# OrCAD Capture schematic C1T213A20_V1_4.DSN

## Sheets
1 000_Structure: title: TELINK; rev: V1.4; note: C1T213A20
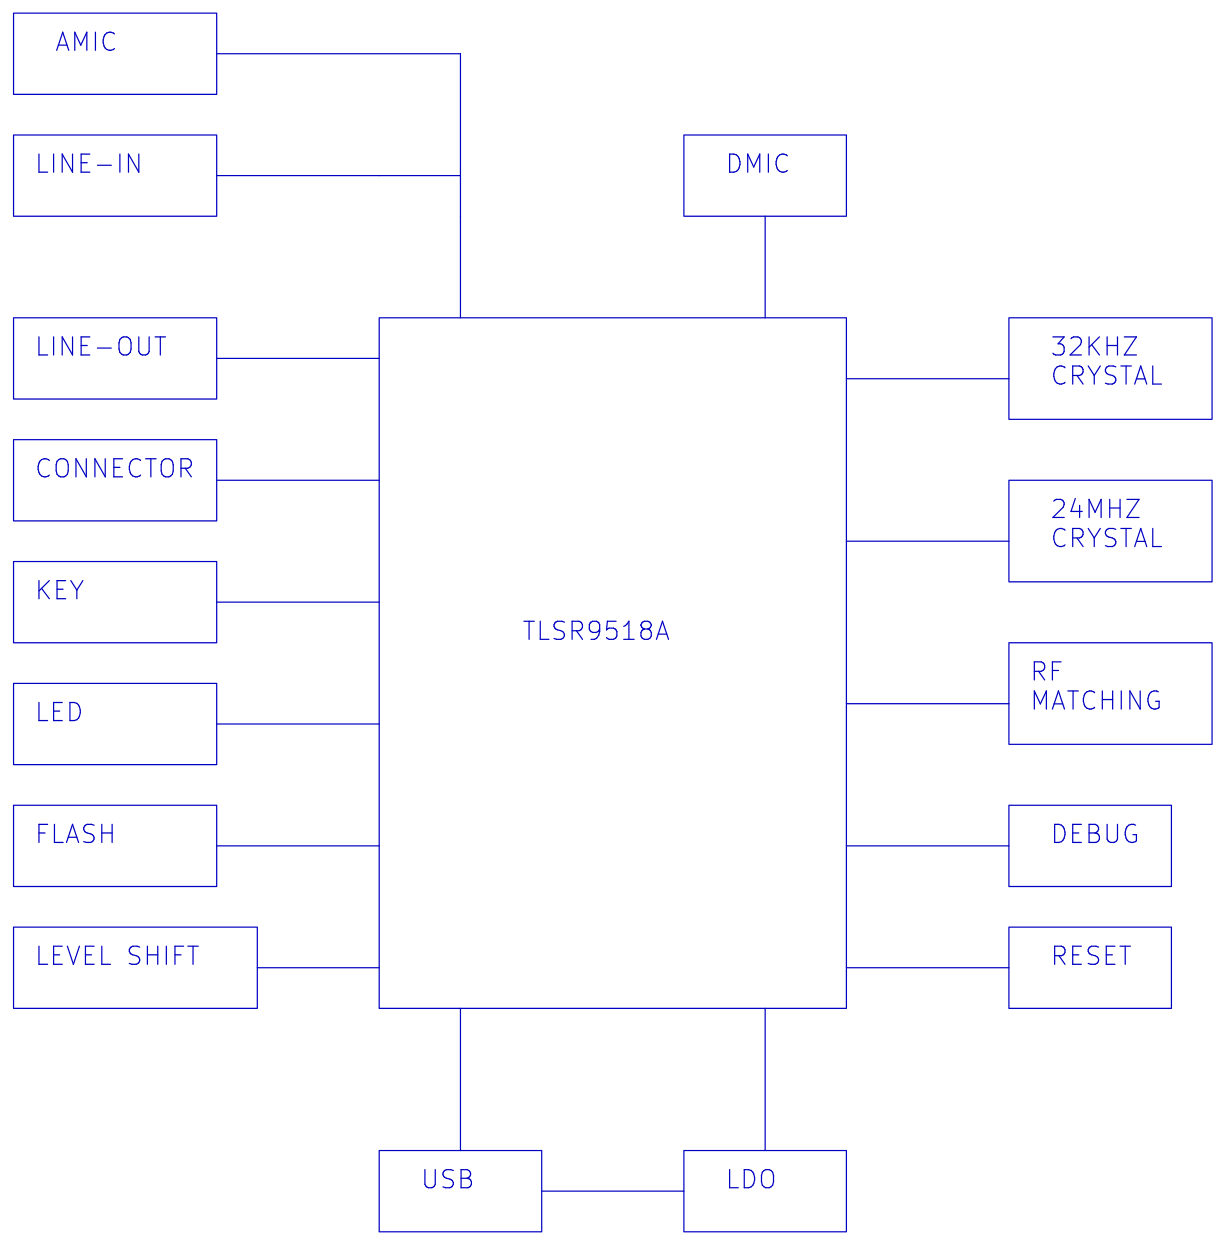
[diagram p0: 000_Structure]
2 002_INTERFACE: size A3
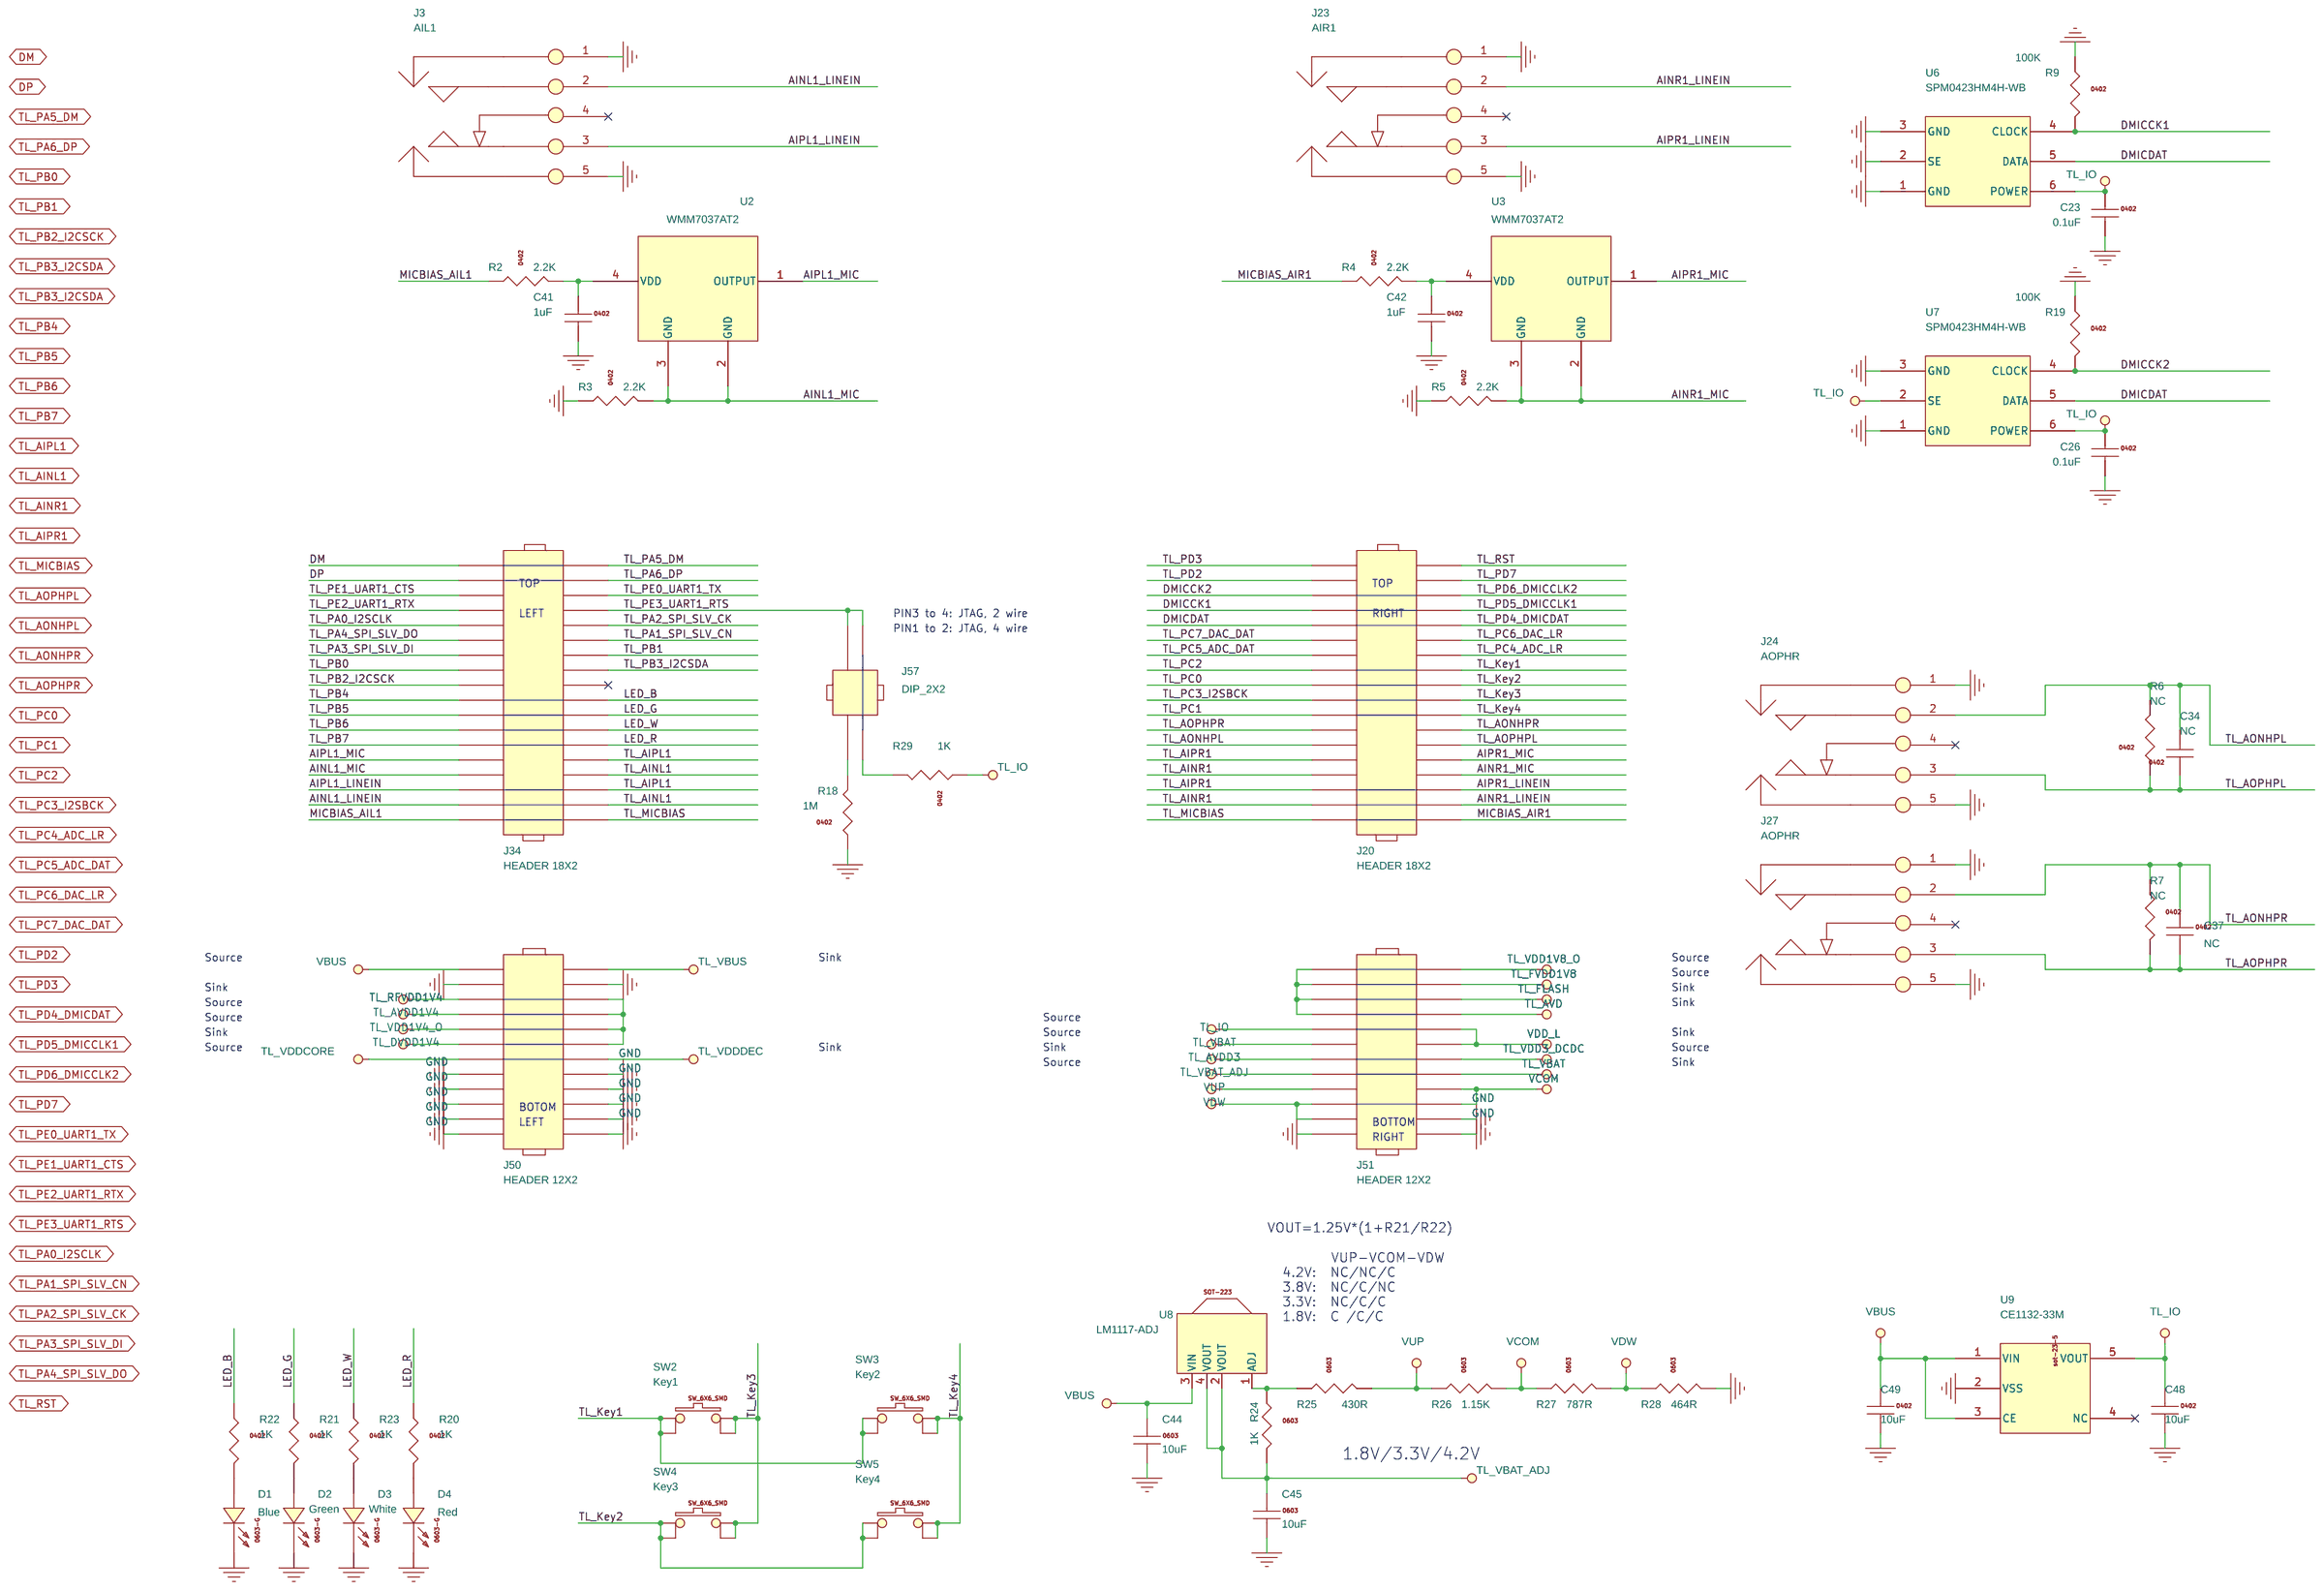
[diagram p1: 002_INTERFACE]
3 000_Log
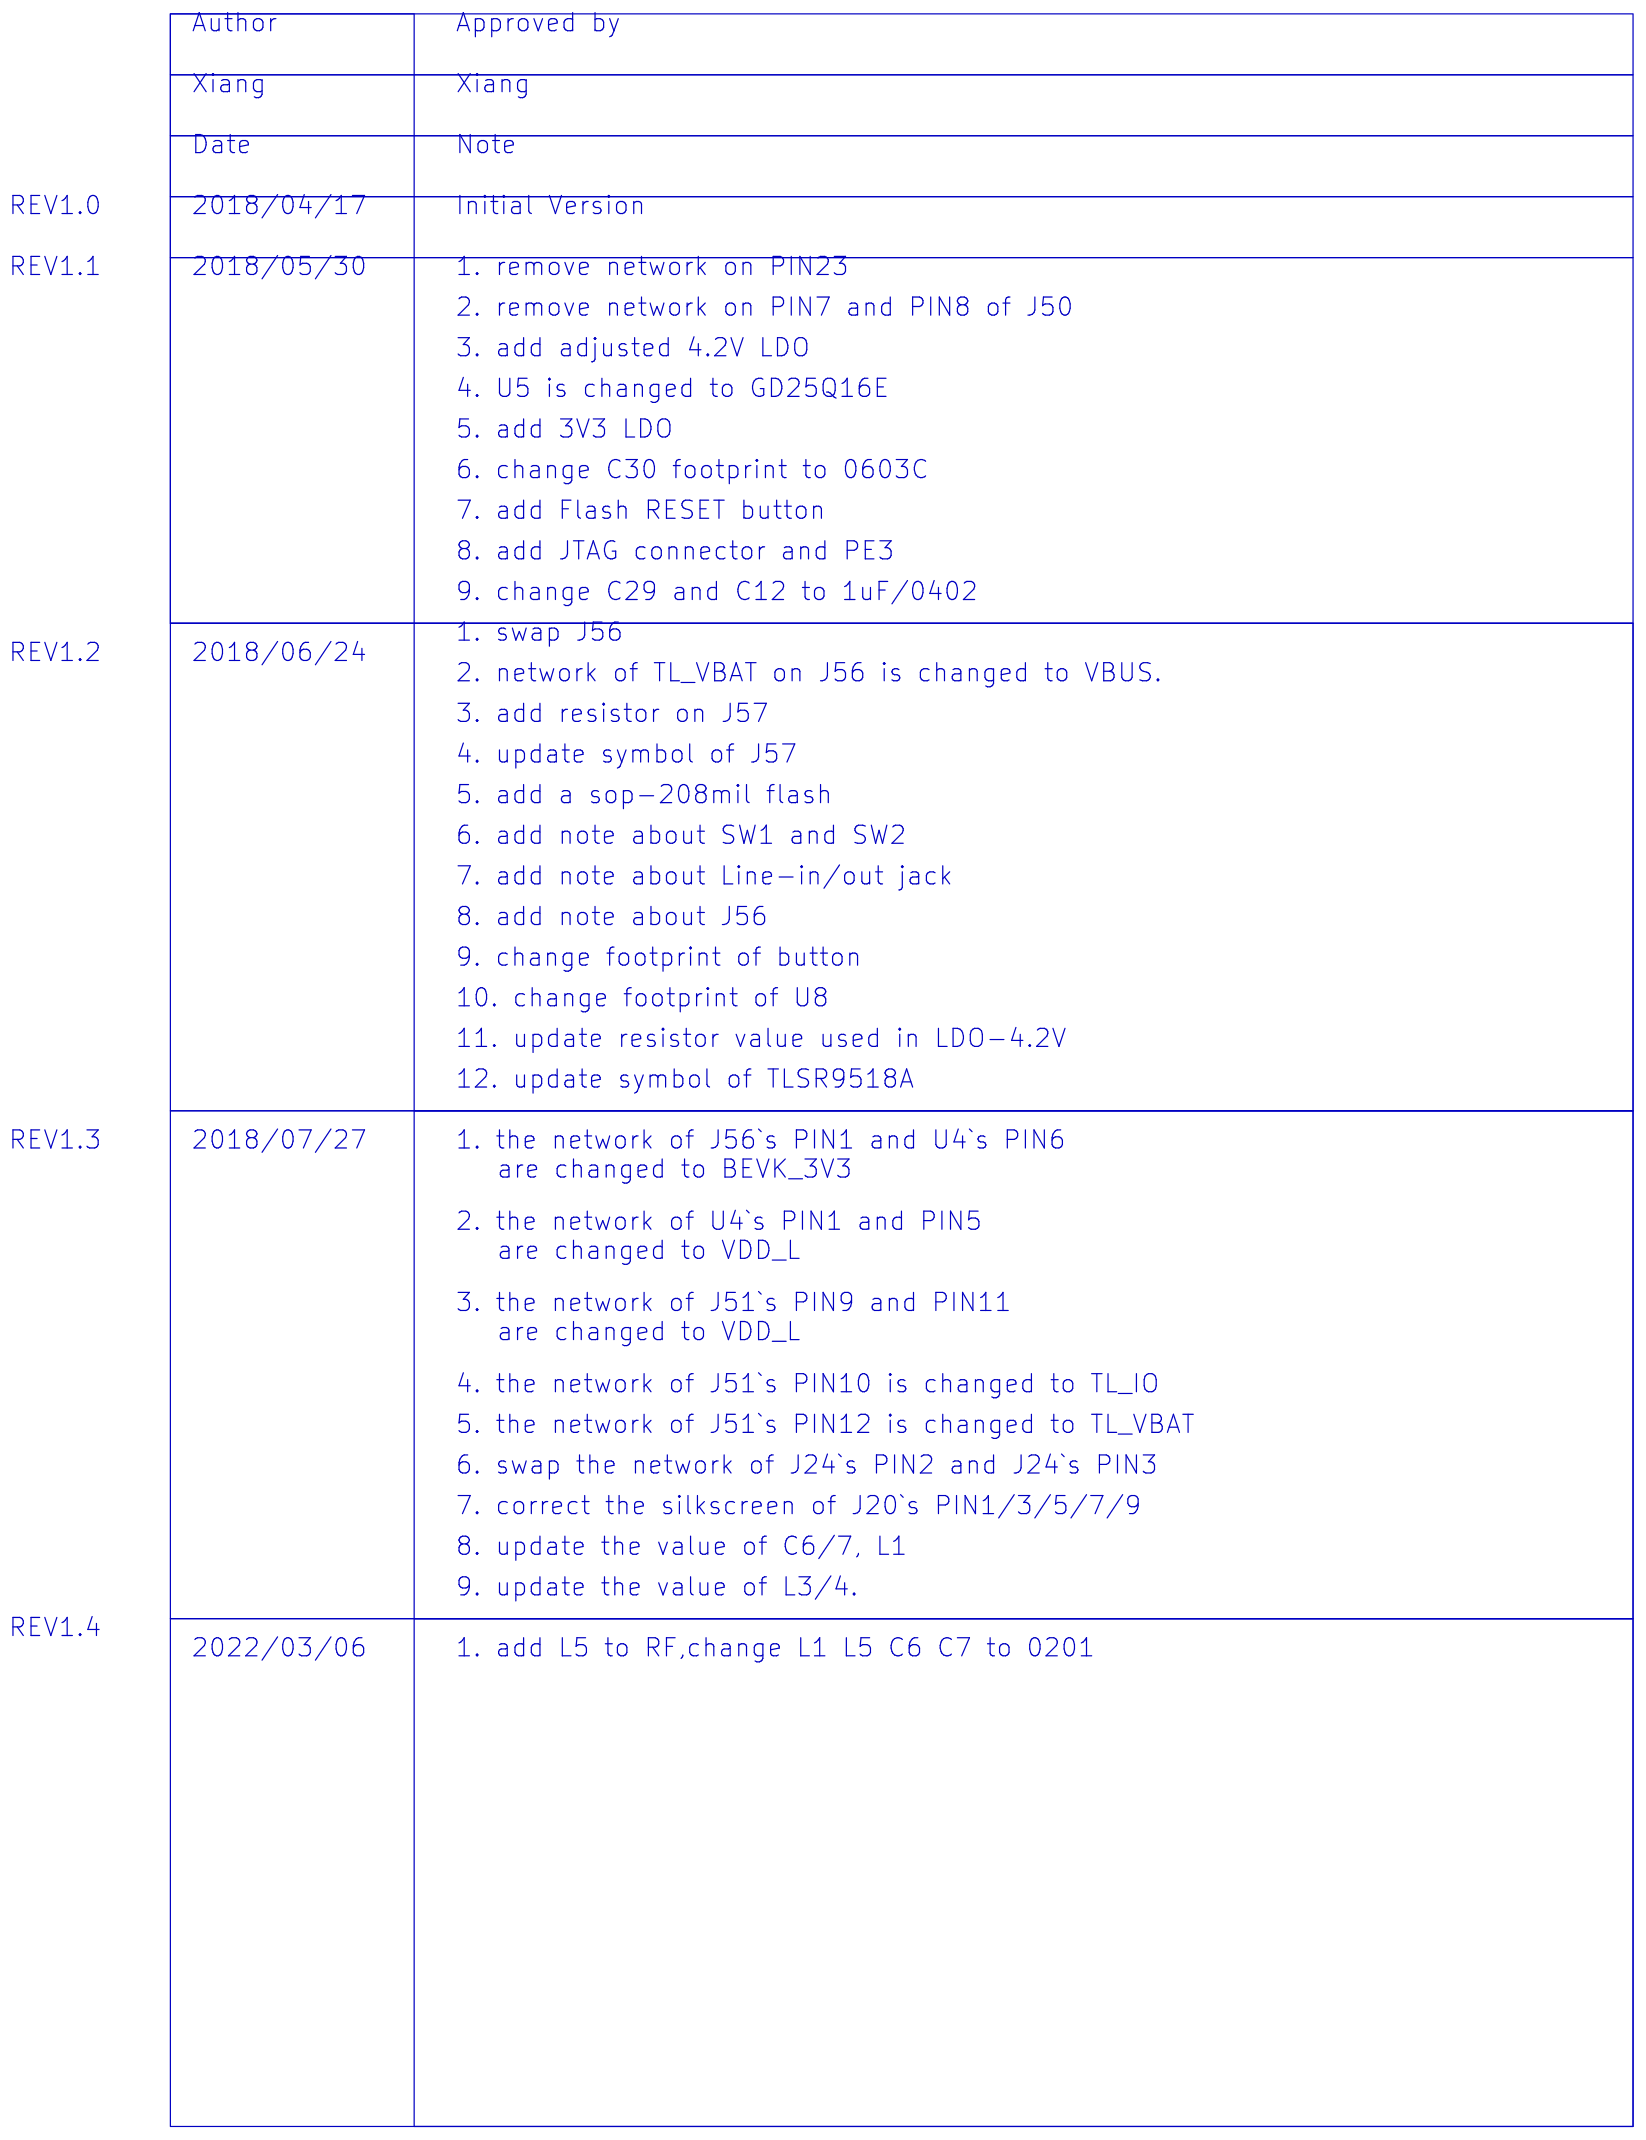
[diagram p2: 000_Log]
4 001_MAIN: size A3
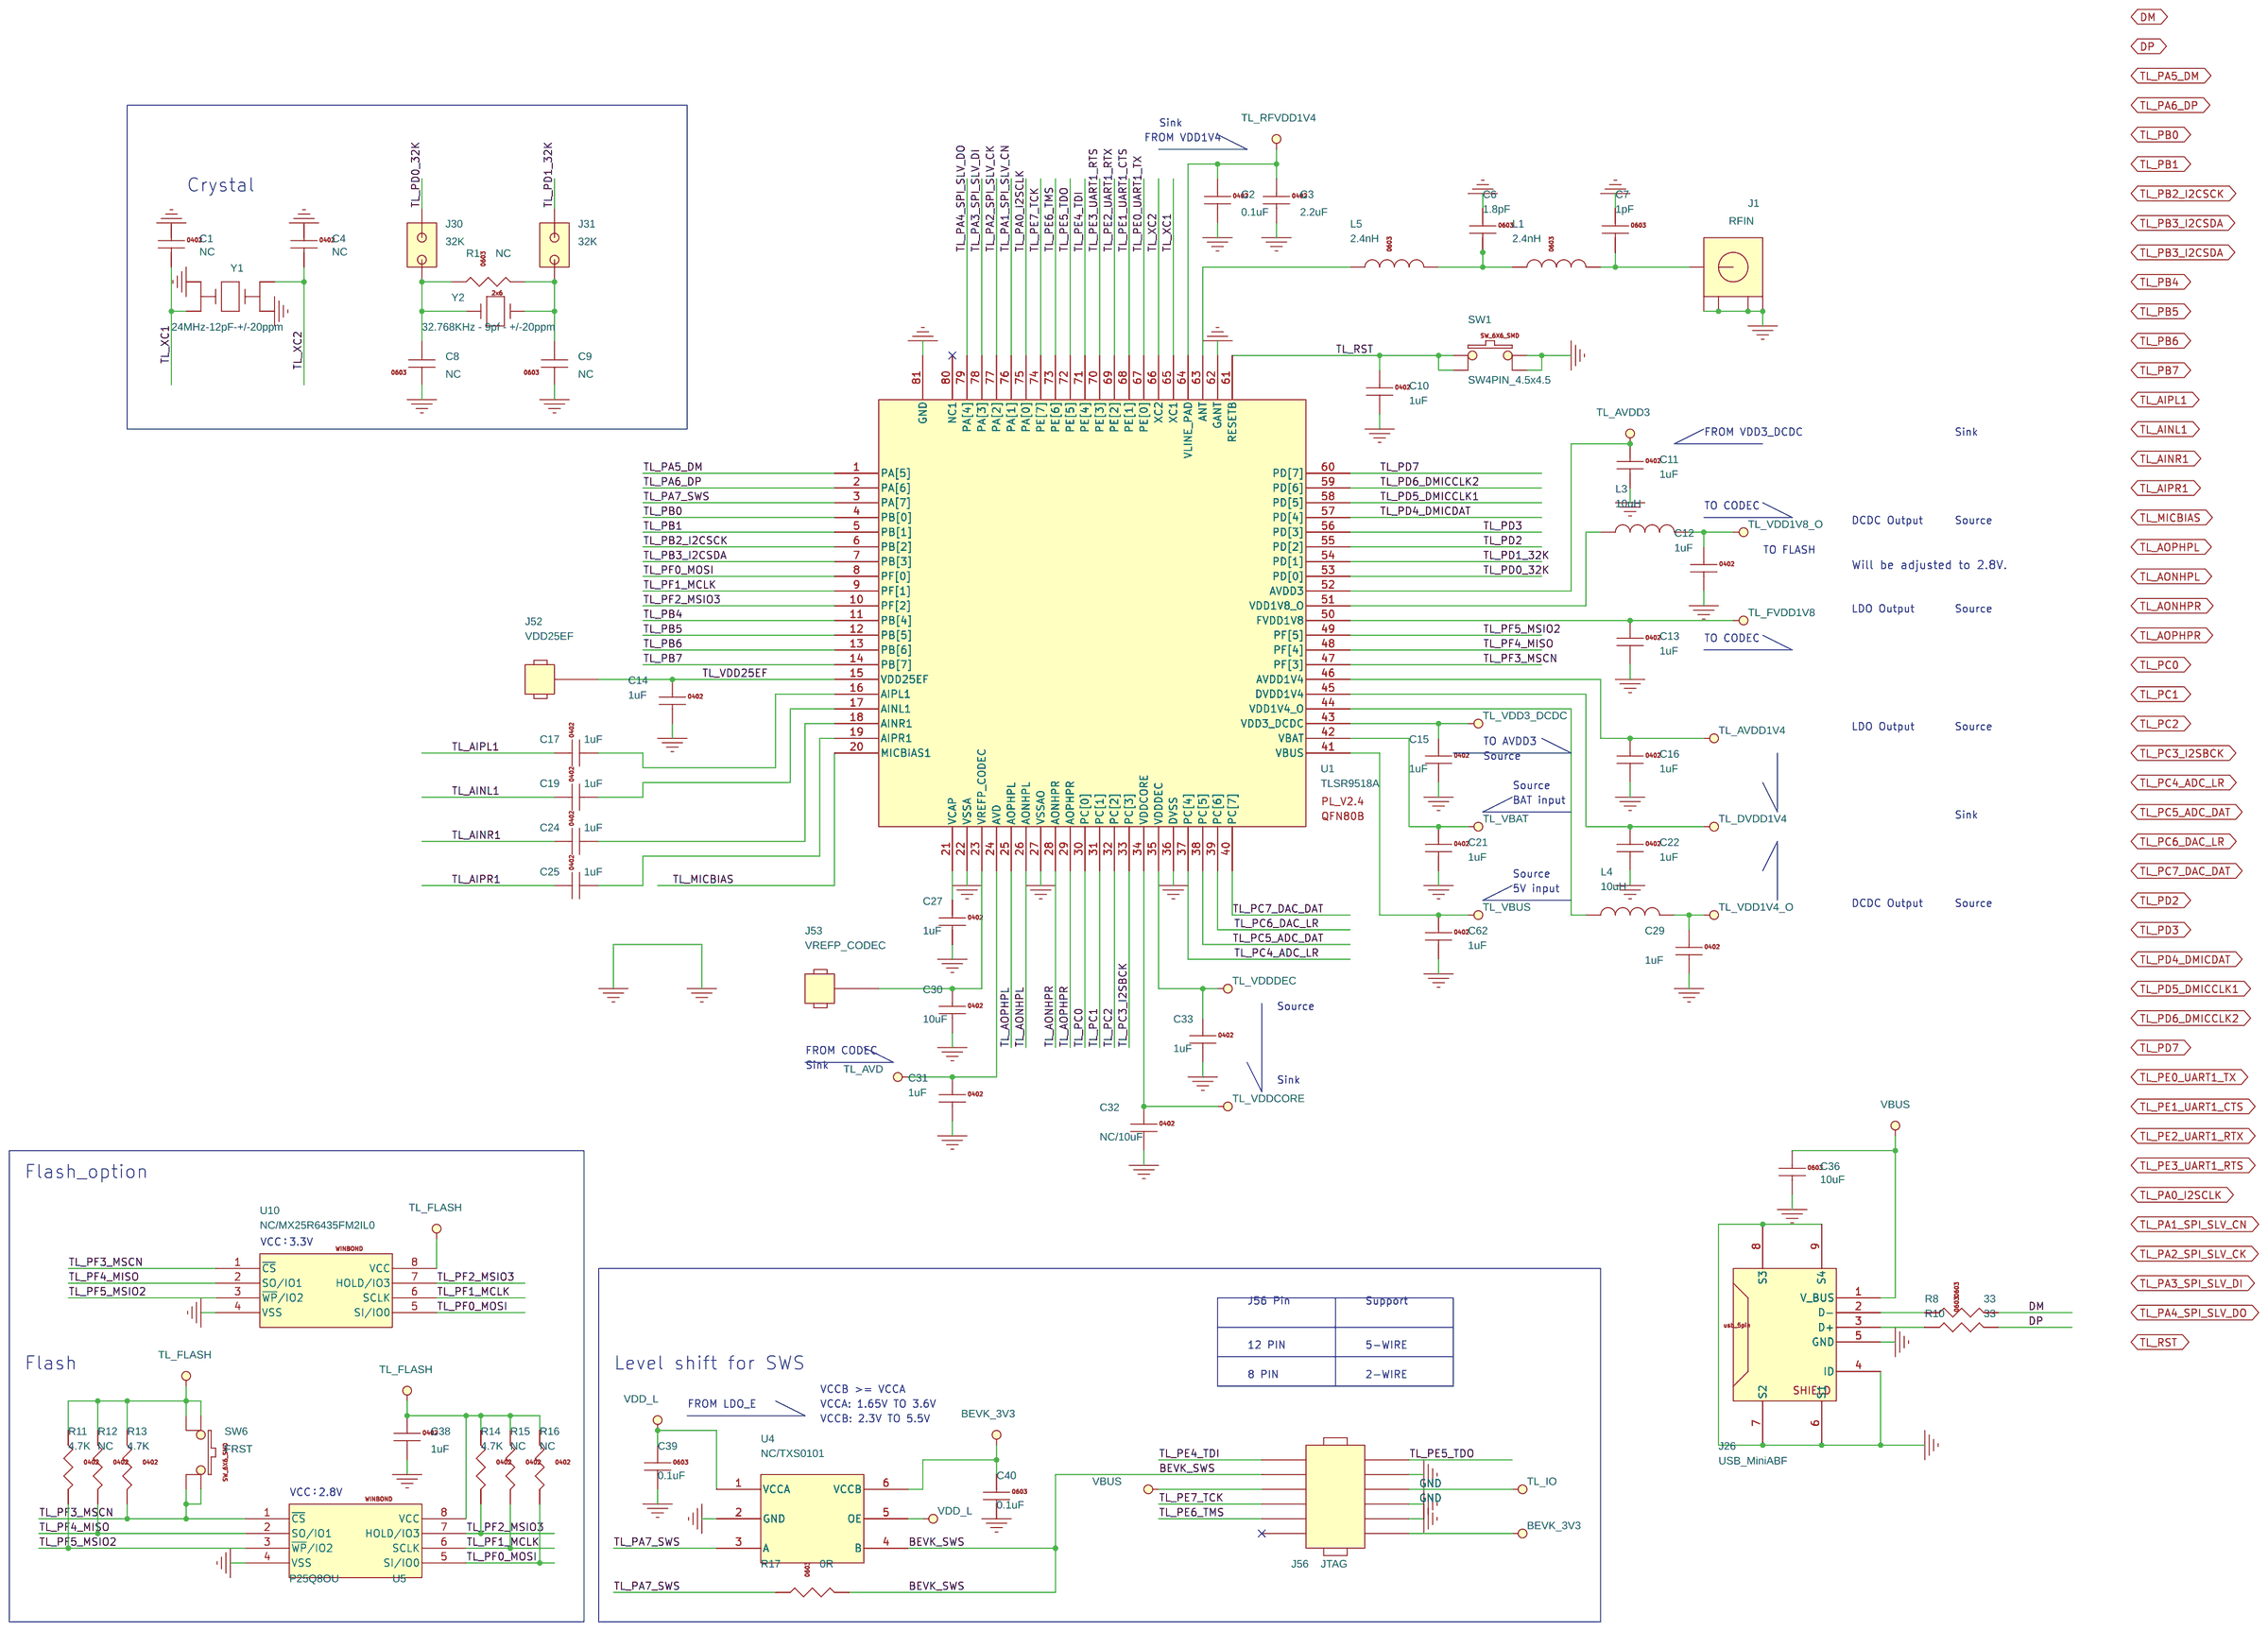
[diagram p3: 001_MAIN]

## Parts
sheet 001_MAIN
C1  NC  [0402]
C2  0.1uF  [0402]
C3  2.2uF  [0402]
C4  NC  [0402]
C6  1.8pF  [0201]
C7  1pF  [0201]
C8  NC  [0402]
C9  NC  [0402]
C10  1uF  [0402]
C11  1uF  [0402]
C12  1uF  [0402]
C13  1uF  [0402]
C14  1uF  [0402]
C15  1uF  [0402]
C16  1uF  [0402]
C17  1uF  [0402]
C19  1uF  [0402]
C21  1uF  [0402]
C22  1uF  [0402]
C24  1uF  [0402]
C25  1uF  [0402]
C27  1uF  [0402]
C29  1uF  [0402]
C30  10uF  [0603C]
C31  1uF  [0402]
C32  NC/10uF  [0603C]
C33  1uF  [0402]
C36  10uF  [0603C]
C38  1uF  [0402]
C39  0.1uF  [0402]
C40  0.1uF  [0402]
C62  1uF  [0402]
J1  RFIN  [SMA-H]
J26  USB_MiniABF  [USB-MINI-F5]
J30  32K  [HDR254F-1X2X850]
J31  32K  [HDR254F-1X2X850]
J52  VDD25EF  [hdr254f-1x1x850]
J53  VREFP_CODEC  [hdr254f-1x1x850]
J56  JTAG  [hdr254f-2x6x850]
L1  2.4nH  [0201]
L3  10uH  [0805L]
L4  10uH  [0805L]
L5  2.4nH  [0201]
R1  NC  [0402]
R8  33  [0402R]
R10  33  [0402R]
R11  4.7K  [0402]
R12  NC  [0402]
R13  4.7K  [0402]
R14  4.7K  [0402]
R15  NC  [0402]
R16  NC  [0402]
R17  0R  [0402R]
SW1  SW4PIN_4.5x4.5  [SW_6X6_SMD]
SW6  FRST  [SW_6X6_SMD]
U1  TLSR9518A  [qfn_9x9_80pin_0p4_6p10x6p10]
U4  NC/TXS0101  [sc70-6]
U5  P25Q8OU  [W25X10_20_40BL]
U10  NC/MX25R6435FM2IL0  [sop8_208mil]
Y1  24MHz-12pF-+/-20ppm  [OSCCC250X320X110]
Y2  32.768KHz - 9pf - +/-20ppm  [OSC_2x6]
sheet 002_INTERFACE
C23  0.1uF  [0402]
C26  0.1uF  [0402]
C34  NC  [0402]
C37  NC  [0402]
C41  1uF  [0402]
C42  1uF  [0402]
C44  10uF  [0603c]
C45  10uF  [0603C]
C48  10uF  [0603C]
C49  10uF  [0603C]
D1  Blue  [0603-LED]
D2  Green  [0603-LED]
D3  White  [0603-LED]
D4  Red  [0603-LED]
J3  AIL1  [PJ-327]
J20  HEADER 18X2  [smd254m-2x18_rx1_30y2_40]
J23  AIR1  [PJ-327]
J24  AOPHR  [PJ-327]
J27  AOPHR  [PJ-327]
J34  HEADER 18X2  [smd254m-2x18_rx1_30y2_40]
J50  HEADER 12X2  [smd254m-2x12_rx1_30y2_40]
J51  HEADER 12X2  [smd254m-2x12_rx1_30y2_40]
J57  DIP_2X2  [DipSwitch_2p54_7p62_2x2]
R2  2.2K  [0402]
R3  2.2K  [0402]
R4  2.2K  [0402]
R5  2.2K  [0402]
R6  NC  [0402]
R7  NC  [0402]
R9  100K  [0402]
R18  1M  [0402]
R19  100K  [0402]
R20  1K  [0402]
R21  1K  [0402]
R22  1K  [0402]
R23  1K  [0402]
R24  1K  [0402]
R25  430R  [0402]
R26  1.15K  [0402]
R27  787R  [0402]
R28  464R  [0402]
R29  1K  [0402]
SW2  Key1  [SW_6X6_SMD]
SW3  Key2  [SW_6X6_SMD]
SW4  Key3  [SW_6X6_SMD]
SW5  Key4  [SW_6X6_SMD]
U2  WMM7037AT2  [ga_bfa423_a83]
U3  WMM7037AT2  [ga_bfa423_a83]
U6  SPM0423HM4H-WB  [DMIC_SPM0423HM4H-WB]
U7  SPM0423HM4H-WB  [DMIC_SPM0423HM4H-WB]
U8  LM1117-ADJ  [sot-223]
U9  CE1132-33M  [sot-23-5]

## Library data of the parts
C1 C4 = C1005_NC
C2 C3 C10-C16 C21-C23 C26 C27 C29-C33 C38 C41 C42 C48 C49 C62 = C1005X5R1C104K
C6-C9 = C1608_NC
C17 C19 C24 C25 C34 C37 = C1005X5R1C105K
C36 C44 = C1608X5R0J106M
C39 C40 C45 = C1608X5R1C105M
J1 = SMA_JACK_2: PART: RF
J26 = USB_MiniABF_5pin
J30 J31 = B2S_3: PAGE: POWER
J52 J53 = HEADER_1
J56 = HEADER_6X2
L1 L5 = MLK1608_000R
L3 L4 = IND
R1 R17 = RS0603K102JT
R8 R10 = RS0603K330JT
R2-R7 R9 R11-R16 R18 R19 R29 = RS0402K104JT
SW1 = SW_6X6_SMD_0
SW2-SW6 = SW_6X6_SMD
U1 = TLSR9518A
U4 = TXS0101
U5 U10 = GD25LD40C_0
Y1 = CRYSTAL4_SM_0
Y2 = OSC_2x6_2pin_16Mhz
D1-D4 = 0603D_Green
J3 J23 J24 J27 = PJ327_2
J20 J34 = HEADER_18X2
J50 J51 = HEADER_12X2
J57 = HEADER_2X2_0
R20-R23 = RS0402K102JT
R24-R28 = RS0603K104JT
U2 U3 = MULPS4CX-RM5_0
U6 U7 = LD1117_SO_0
U8 = XC62FP3302_0.3V_SOT-89
U9 = XC6219_6.3V_SOT-23-5

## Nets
VBUS: C36.1 C44.1 C49.1 J26.1(V_BUS) J50.2 J56.8 U8.3(VIN) U9.1(VIN) U9.3(CE)
VDD_L: C39.1 J51.9 J51.11 U4.1(VCCA) U4.5(OE)
0: C1.1 C2.2 C3.2 C4.1 C6.1 C7.1 C8.1 C9.1 C10.2 C11.2 C12.2 C13.2 C14.2 C15.2 C16.2 C21.2 C22.2 C23.2 C26.2 C27.2 C29.2 C30.2 C31.2 C32.2 C33.2 C36.2 C38.2 C39.2 C40.2 C41.2 C42.2 C44.2 C45.2 C48.2 C49.2 C62.2 D1.C(CATHODE) D2.C(CATHODE) D3.C(CATHODE) D4.C(CATHODE) J1.2 J1.3 J1.4 J1.5 J3.1 J3.5 J23.1 J23.5 J24.1 J24.5 J26.4(ID) J26.5(GND) J26.6(S1) J26.7(S2) J26.8(S3) J26.9(S4) J27.1 J27.5 J50.3 J50.4 J50.15 J50.16 J50.17 J50.18 J50.19 J50.20 J50.21 J50.22 J50.23 J50.24 J51.21 J51.23 J51.24 J56.3 J56.5 J56.9 R3.1 R5.1 R9.1 R18.1 R19.1 R28.2 SW1.3 SW1.4 U1.22(VSSA) U1.27(VSSAO) U1.36(DVSS) U1.62(GANT) U1.81(GND) U4.2(GND) U5.4(VSS) U6.1(GND) U6.2(SE) U6.3(GND) U7.1(GND) U7.3(GND) U9.2(VSS) U10.4(VSS) Y1.2 Y1.4
AINL1_LINEIN: J3.2 J34.34
AINL1_MIC: J34.30 R3.2 U2.2(GND) U2.3(GND)
AINR1_LINEIN: J20.33 J23.2
AINR1_MIC: J20.29 R5.2 U3.2(GND) U3.3(GND)
AIPL1_LINEIN: J3.3 J34.32
AIPL1_MIC: J34.28 U2.1(OUTPUT)
AIPR1_LINEIN: J20.31 J23.3
AIPR1_MIC: J20.27 U3.1(OUTPUT)
BEVK_3V3: C40.1 J56.1 U4.6(VCCB)
BEVK_SWS: J56.10 R17.2 U4.4(B)
DM: R8.2
DM (page 002_INTERFACE): J34.2
DMICCK1: J20.8 R9.2 U6.4(CLOCK)
DMICCK2: J20.6 R19.2 U7.4(CLOCK)
DMICDAT: J20.10 U6.5(DATA) U7.5(DATA)
DP: R10.2
DP (page 002_INTERFACE): J34.4
LED_B: J34.19 R22.1
LED_G: J34.21 R21.1
LED_R: J34.25 R20.1
LED_W: J34.23 R23.1
MICBIAS_AIL1: J34.36 R2.1
MICBIAS_AIR1: J20.35 R4.1
TL_AINL1: C19.1
TL_AINL1 (page 002_INTERFACE): J34.29 J34.33
TL_AINR1: C24.1
TL_AINR1 (page 002_INTERFACE): J20.30 J20.34
TL_AIPL1: C17.1
TL_AIPL1 (page 002_INTERFACE): J34.27 J34.31
TL_AIPR1: C25.1
TL_AIPR1 (page 002_INTERFACE): J20.28 J20.32
TL_AONHPL: U1.26(AONHPL)
TL_AONHPL (page 002_INTERFACE): C34.2 J20.26 J24.2 R6.2
TL_AONHPR: U1.28(AONHPR)
TL_AONHPR (page 002_INTERFACE): C37.1 J20.23 J27.2 R7.1
TL_AOPHPL: U1.25(AOPHPL)
TL_AOPHPL (page 002_INTERFACE): C34.1 J20.25 J24.3 R6.1
TL_AOPHPR: U1.29(AOPHPR)
TL_AOPHPR (page 002_INTERFACE): C37.2 J20.24 J27.3 R7.2
TL_AVD: C31.1 J51.7 U1.24(AVD)
TL_AVDD1V4: C16.1 J50.8 U1.46(AVDD1V4)
TL_AVDD3: C11.1 J51.14 U1.52(AVDD3)
TL_DVDD1V4: C22.1 J50.12 U1.45(DVDD1V4)
TL_FLASH: C38.1 J51.5 R11.1 R12.1 R13.1 R14.1 R15.1 R16.1 SW6.1 SW6.2 U5.8(VCC) U10.8(VCC)
TL_FVDD1V8: C13.1 J51.3 U1.50(FVDD1V8)
TL_IO: C23.1 C26.1 C48.1 J51.10 J56.7 R29.1 U6.6(POWER) U7.2(SE) U7.6(POWER) U9.5(VOUT)
TL_Key1: J20.15 SW2.1 SW2.2 SW3.1 SW3.2
TL_Key2: J20.17 SW4.1 SW4.2 SW5.1 SW5.2
TL_Key3: J20.19 SW2.3 SW2.4 SW4.3 SW4.4
TL_Key4: J20.21 SW3.3 SW3.4 SW5.3 SW5.4
TL_MICBIAS: U1.20(MICBIAS1)
TL_MICBIAS (page 002_INTERFACE): J20.36 J34.35
TL_PA0_I2SCLK: U1.75(PA[0])
TL_PA0_I2SCLK (page 002_INTERFACE): J34.10
TL_PA1_SPI_SLV_CN: U1.76(PA[1])
TL_PA1_SPI_SLV_CN (page 002_INTERFACE): J34.11
TL_PA2_SPI_SLV_CK: U1.77(PA[2])
TL_PA2_SPI_SLV_CK (page 002_INTERFACE): J34.9
TL_PA3_SPI_SLV_DI: U1.78(PA[3])
TL_PA3_SPI_SLV_DI (page 002_INTERFACE): J34.14
TL_PA4_SPI_SLV_DO: U1.79(PA[4])
TL_PA4_SPI_SLV_DO (page 002_INTERFACE): J34.12
TL_PA5_DM: U1.1(PA[5])
TL_PA5_DM (page 002_INTERFACE): J34.1
TL_PA6_DP: U1.2(PA[6])
TL_PA6_DP (page 002_INTERFACE): J34.3
TL_PA7_SWS: R17.1 U1.3(PA[7]) U4.3(A)
TL_PB0: U1.4(PB[0])
TL_PB0 (page 002_INTERFACE): J34.16
TL_PB1: U1.5(PB[1])
TL_PB1 (page 002_INTERFACE): J34.13
TL_PB2_I2CSCK: U1.6(PB[2])
TL_PB2_I2CSCK (page 002_INTERFACE): J34.18
TL_PB3_I2CSDA: U1.7(PB[3])
TL_PB3_I2CSDA (page 002_INTERFACE): J34.15
TL_PB4: U1.11(PB[4])
TL_PB4 (page 002_INTERFACE): J34.20
TL_PB5: U1.12(PB[5])
TL_PB5 (page 002_INTERFACE): J34.22
TL_PB6: U1.13(PB[6])
TL_PB6 (page 002_INTERFACE): J34.24
TL_PB7: U1.14(PB[7])
TL_PB7 (page 002_INTERFACE): J34.26
TL_PC0: U1.30(PC[0])
TL_PC0 (page 002_INTERFACE): J20.18
TL_PC1: U1.31(PC[1])
TL_PC1 (page 002_INTERFACE): J20.22
TL_PC2: U1.32(PC[2])
TL_PC2 (page 002_INTERFACE): J20.16
TL_PC3_I2SBCK: U1.33(PC[3])
TL_PC3_I2SBCK (page 002_INTERFACE): J20.20
TL_PC4_ADC_LR: U1.37(PC[4])
TL_PC4_ADC_LR (page 002_INTERFACE): J20.13
TL_PC5_ADC_DAT: U1.38(PC[5])
TL_PC5_ADC_DAT (page 002_INTERFACE): J20.14
TL_PC6_DAC_LR: U1.39(PC[6])
TL_PC6_DAC_LR (page 002_INTERFACE): J20.11
TL_PC7_DAC_DAT: U1.40(PC[7])
TL_PC7_DAC_DAT (page 002_INTERFACE): J20.12
TL_PD0_32K: J30.2 U1.53(PD[0])
TL_PD1_32K: J31.2 U1.54(PD[1])
TL_PD2: U1.55(PD[2])
TL_PD2 (page 002_INTERFACE): J20.4
TL_PD3: U1.56(PD[3])
TL_PD3 (page 002_INTERFACE): J20.2
TL_PD4_DMICDAT: U1.57(PD[4])
TL_PD4_DMICDAT (page 002_INTERFACE): J20.9
TL_PD5_DMICCLK1: U1.58(PD[5])
TL_PD5_DMICCLK1 (page 002_INTERFACE): J20.7
TL_PD6_DMICCLK2: U1.59(PD[6])
TL_PD6_DMICCLK2 (page 002_INTERFACE): J20.5
TL_PD7: U1.60(PD[7])
TL_PD7 (page 002_INTERFACE): J20.3
TL_PE0_UART1_TX: U1.67(PE[0])
TL_PE0_UART1_TX (page 002_INTERFACE): J34.5
TL_PE1_UART1_CTS: U1.68(PE[1])
TL_PE1_UART1_CTS (page 002_INTERFACE): J34.6
TL_PE2_UART1_RTX: U1.69(PE[2])
TL_PE2_UART1_RTX (page 002_INTERFACE): J34.8
TL_PE3_UART1_RTS: U1.70(PE[3])
TL_PE3_UART1_RTS (page 002_INTERFACE): J34.7 J57.1 J57.3
TL_PE4_TDI: J56.12 U1.71(PE[4])
TL_PE5_TDO: J56.11 U1.72(PE[5])
TL_PE6_TMS: J56.4 U1.73(PE[6])
TL_PE7_TCK: J56.6 U1.74(PE[7])
TL_PF0_MOSI: R16.2 U1.8(PF[0]) U5.5(SI/IO0) U10.5(SI/IO0)
TL_PF1_MCLK: R15.2 U1.9(PF[1]) U5.6(SCLK) U10.6(SCLK)
TL_PF2_MSIO3: R14.2 U1.10(PF[2]) U5.7(HOLD/IO3) U10.7(HOLD/IO3)
TL_PF3_MSCN: R13.2 SW6.3 SW6.4 U1.47(PF[3]) U5.1(~{CS}) U10.1(~{CS})
TL_PF4_MISO: R12.2 U1.48(PF[4]) U5.2(SO/IO1) U10.2(SO/IO1)
TL_PF5_MSIO2: R11.2 U1.49(PF[5]) U5.3(~{WP}/IO2) U10.3(~{WP}/IO2)
TL_RFVDD1V4: C2.1 C3.1 J50.6 U1.64(VLINE_PAD)
TL_RST: C10.1 SW1.1 SW1.2 U1.61(RESETB)
TL_RST (page 002_INTERFACE): J20.1
TL_VBAT: C21.1 J51.12 J51.15 U1.42(VBAT)
TL_VBAT_ADJ: C45.1 J51.16 R24.2 U8.2(VOUT) U8.4(VOUT)
TL_VBUS: C62.1 J50.1 U1.41(VBUS)
TL_VDD1V4_O: C29.1 J50.10 L4.2
TL_VDD1V8_O: C12.1 J51.1 L3.2
TL_VDD3_DCDC: C15.1 J51.13 U1.43(VDD3_DCDC)
TL_VDD25EF: C14.1 J52.1 U1.15(VDD25EF)
TL_VDDCORE: C32.1 J50.14 U1.34(VDDCORE)
TL_VDDDEC: C33.1 J50.13 U1.35(VDDDEC)
TL_XC1: C1.2 U1.65(XC1) Y1.3
TL_XC2: C4.2 U1.66(XC2) Y1.1
VCOM: J51.17 J51.19 R26.2 R27.1
VDW: J51.20 J51.22 R27.2 R28.1
VUP: J51.18 R25.2 R26.1
N19754780: J26.3(D+) R10.1
N19754798: J26.2(D-) R8.1
N19860865: C8.2 J30.1 R1.1 Y2.1
N19860867: C9.2 J31.1 R1.2 Y2.2
N19861195: C24.2 U1.18(AINR1)
N19861200: C25.2 U1.19(AIPR1)
N19861219: C30.1 J53.1 U1.23(VREFP_CODEC)
N19861425: C19.2 U1.17(AINL1)
N19861431: C17.2 U1.16(AIPL1)
N19861467: C27.1 U1.21(VCAP)
N19861531: L3.1 U1.51(VDD1V8_O)
N19861571: L4.1 U1.44(VDD1V4_O)
N19870648: R24.1 R25.1 U8.1(ADJ)
N19912632: C42.1 R4.2 U3.4(VDD)
N19912698: C41.1 R2.2 U2.4(VDD)
N19916631: J57.4 R29.2
N19927561: J50.5 J50.7 J50.9 J50.11
N19931796: J51.2 J51.4 J51.6 J51.8
N19937731: J57.2 R18.2
N19956971: L5.1 U1.63(ANT)
N19968425: D2.A(ANODE) R21.2
N19968437: D1.A(ANODE) R22.2
N19968439: D4.A(ANODE) R20.2
N19968446: D3.A(ANODE) R23.2
N19973210: C7.2 J1.1 L1.2
N19973218: C6.2 L1.1 L5.2

Not connected (* = marked no-connect by the designer): J3 4*; J23 4*; J24 4*; J27 4*; J34 17*; J56 2*; U1 80(NC1)*; U9 4(NC)*

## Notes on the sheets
sheet 1
- AMIC
- LINE-IN
- DMIC
- LINE-OUT
- 32KHZ
  CRYSTAL
- CONNECTOR
- 24MHZ
  CRYSTAL
- KEY
- TLSR9518A
- RF
  MATCHING
- LED
- FLASH
- DEBUG
- LEVEL SHIFT
- RESET
- USB
- LDO
sheet 2
- TOP
- TOP
- LEFT
- PIN3 to 4: JTAG, 2 wire
- RIGHT
- PIN1 to 2: JTAG, 4 wire
- Source
- Sink
- Source
- Source
- Sink
- Sink
- Source
- Sink
- Source
- Source
- Sink
- Source
- Sink
- Sink
- Source
- Sink
- Source
- Source
- Sink
- BOTOM
- LEFT
- BOTTOM
- RIGHT
- VOUT=1.25V*(1+R21/R22)
- VUP-VCOM-VDW
  4.2V:  NC/NC/C
  3.8V:  NC/C/NC
  3.3V:  NC/C/C
  1.8V:  C /C/C
- 1.8V/3.3V/4.2V
sheet 3
- Author
- Approved by
- Xiang
- Xiang
- Date
- Note
- REV1.0
- 2018/04/17
- Initial Version
- REV1.1
- 2018/05/30
- 1. remove network on PIN23
- 2. remove network on PIN7 and PIN8 of J50
- 3. add adjusted 4.2V LDO
- 4. U5 is changed to GD25Q16E
- 5. add 3V3 LDO
- 6. change C30 footprint to 0603C
- 7. add Flash RESET button
- 8. add JTAG connector and PE3
- 9. change C29 and C12 to 1uF/0402
- 1. swap J56
- REV1.2
- 2018/06/24
- 2. network of TL_VBAT on J56 is changed to VBUS.
- 3. add resistor on J57
- 4. update symbol of J57
- 5. add a sop-208mil flash
- 6. add note about SW1 and SW2
- 7. add note about Line-in/out jack
- 8. add note about J56
- 9. change footprint of button
- 10. change footprint of U8
- 11. update resistor value used in LDO-4.2V
- 12. update symbol of TLSR9518A
- REV1.3
- 2018/07/27
- 1. the network of J56`s PIN1 and U4`s PIN6
     are changed to BEVK_3V3
- 2. the network of U4`s PIN1 and PIN5
     are changed to VDD_L
- 3. the network of J51`s PIN9 and PIN11
     are changed to VDD_L
- 4. the network of J51`s PIN10 is changed to TL_IO
- 5. the network of J51`s PIN12 is changed to TL_VBAT
- 6. swap the network of J24`s PIN2 and J24`s PIN3
- 7. correct the silkscreen of J20`s PIN1/3/5/7/9
- 8. update the value of C6/7, L1
- 9. update the value of L3/4.
- REV1.4
- 2022/03/06
- 1. add L5 to RF,change L1 L5 C6 C7 to 0201
sheet 4
- Sink
- FROM VDD1V4
- Crystal
- FROM VDD3_DCDC
- Sink
- TO CODEC
- DCDC Output
- Source
- TO FLASH
- Will be adjusted to 2.8V.
- LDO Output
- Source
- TO CODEC
- TO AVDD3
- LDO Output
- Source
- Source
- Source
- BAT input
- Sink
- Source
- 5V input
- DCDC Output
- Source
- Source
- FROM CODEC
- Sink
- Sink
- Flash_option
- VCC：3.3V
- J56 Pin
- Support
- 12 PIN
- 5-WIRE
- Flash
- Level shift for SWS
- 8 PIN
- 2-WIRE
- VCCB >= VCCA
- FROM LDO_E
- VCCA: 1.65V TO 3.6V
- VCCB: 2.3V TO 5.5V
- VCC：2.8V
